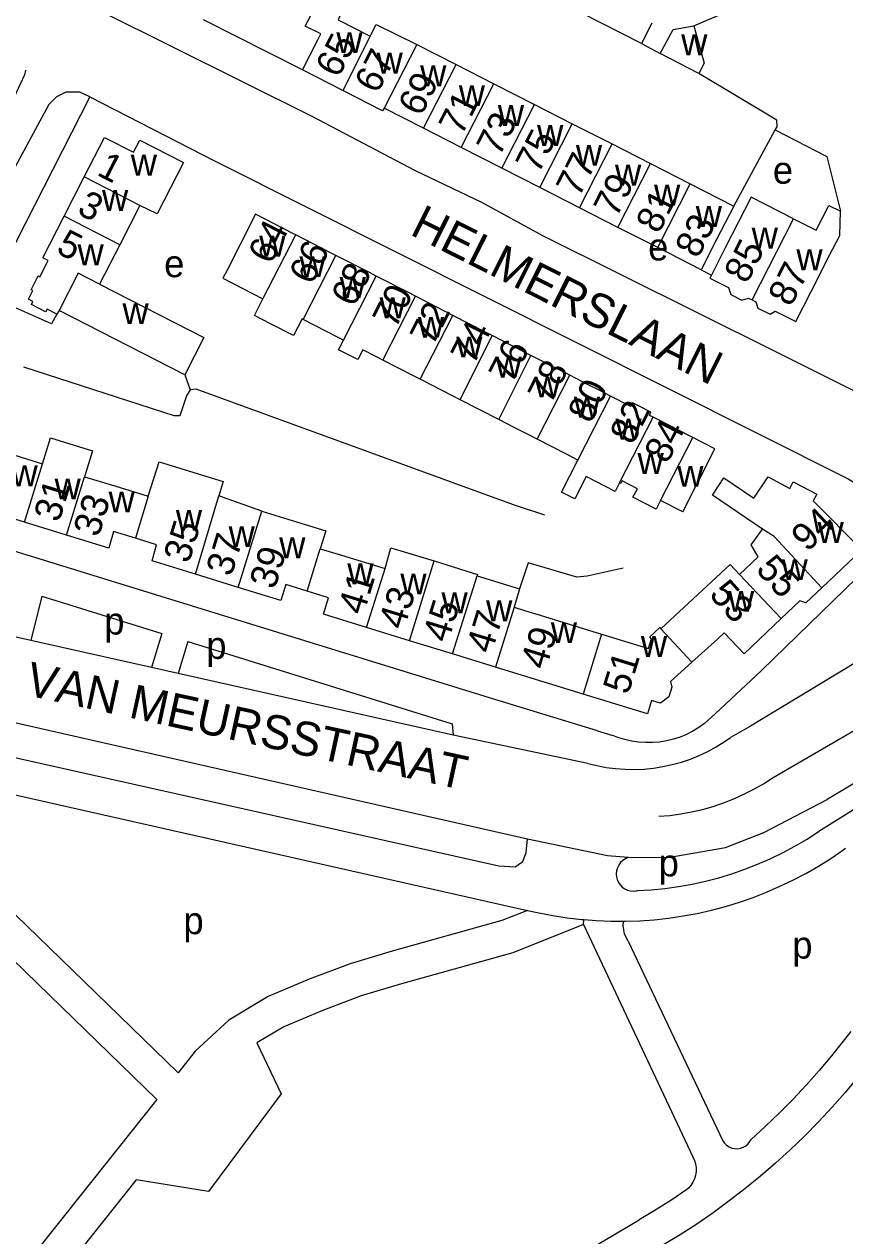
# Model space of a CAD drawing. Extents: x 159700 to 161346, y 381730 to 382922.
# Drawn here: x 161147.7 to 161268.5, y 382139.7 to 382318 of the extents above; entities that cross this region are included whole.
import ezdxf

# ---------------------------------------------------------------- set-up
doc = ezdxf.new("R2010")
doc.units = 0
for name, color, linetype in [('BLT_Basislijn', 7, 'Continuous'), ('BLT_Bebouwing', 7, 'Continuous'), ('BLT_Centroide', 7, 'Continuous'), ('BLT_Huisnummer', 7, 'Continuous'), ('BLT_Huisnummer_ tussenligend', 7, 'Continuous'), ('BLT_Onderverdeling_panden', 7, 'Continuous'), ('BLT_Straatnaam', 7, 'Continuous')]:
    doc.layers.add(name, color=color, linetype=linetype)

msp = doc.modelspace()

# ---------------------------------------------------------------- linework, layer by layer
at = {"layer": 'BLT_Basislijn'}
for p, q in [((161246.29, 382317.8), (161251.01, 382319.8)), ((161188.65, 382311.3), (161174.06, 382318.7)), ((161157.33, 382307.36), (161142.38, 382278.03)), ((161252.16, 382291.27), (161258.27, 382302.47)), ((161247.35, 382281.89), (161248.86, 382281.11)), ((161171.32, 382266.4), (161172.12, 382264.2)), ((161150.27, 382233.83), (161148.65, 382227.32)), ((161150.27, 382233.83), (161167.93, 382228.34)), ((161148.65, 382227.32), (161144.74, 382228.2)), ((161167.93, 382228.34), (161166.4, 382223.34)), ((161257.96, 382207.15), (161294.16, 382228.21)), ((161166.4, 382223.34), (161148.65, 382227.32)), ((161171.75, 382227.15), (161170.32, 382222.46)), ((161273.58, 382226.16), (161254.38, 382214.56)), ((161170.32, 382222.46), (161166.4, 382223.34)), ((161210.83, 382213.38), (161170.32, 382222.46)), ((161232.1, 382213.98), (161215.7, 382219.01)), ((161249.4, 382216.51), (161247.87, 382215.08)), ((161232.1, 382213.98), (161234.33, 382213.33)), ((161254.38, 382214.56), (161251.69, 382213.01)), ((161230.67, 382209.19), (161210.83, 382213.38)), ((161279.52, 382212.11), (161265.92, 382203.87)), ((161122.38, 382209.98), (161221.8, 382187.57)), ((161230.67, 382209.19), (161233.36, 382208.62)), ((161144.83, 382188.45), (161151.35, 382182.11)), ((161230.04, 382185.49), (161230.1, 382186.2)), ((161230.04, 382185.49), (161246.12, 382151.26)), ((161141.19, 382185.02), (161147.87, 382178.52)), ((161151.35, 382182.11), (161170.32, 382163.66)), ((161236.6, 382183.04), (161250.53, 382153.64)), ((161147.87, 382178.52), (161167.19, 382159.73)), ((161269.39, 382169.75), (161266.56, 382166.17)), ((161167.19, 382159.73), (161147.75, 382135.31)), ((161164.16, 382147.9), (161150.96, 382131.31)), ((161226.29, 382134.98), (161238.25, 382142.02))]:
    msp.add_line(p, q, dxfattribs=at)
for points in [[(161298.14, 382325.04), (161299.69, 382317.42), (161300.12, 382311.03), (161299.87, 382302.89), (161298.97, 382296.72), (161298.27, 382293.35), (161296.39, 382286.02), (161292.14, 382276.23), (161285.45, 382261.64), (161283.47, 382257.74), (161282.99, 382257.62), (161282.06, 382257.91), (161259.03, 382269.47)], [(161259.03, 382269.47), (161258.44, 382269.76), (161224.02, 382286.9), (161215.06, 382291.8), (161205.29, 382296.45), (161190.08, 382304.47), (161159.12, 382319.84)], [(161238.56, 382315.19), (161241.34, 382313.71)], [(161147.84, 382311.25), (161147.72, 382310.59), (161145.18, 382305.08)], [(161258.27, 382302.47), (161258.54, 382302.91), (161258.5, 382303.93), (161247.03, 382310.78)], [(161157.33, 382307.36), (161155.87, 382308.04), (161153.79, 382308.04), (161152.42, 382307.37), (161151.3, 382306.22), (161146.63, 382297.57), (161141.2, 382286.87), (161140.09, 382285.05), (161118.46, 382243.46), (161117.44, 382240.72), (161117.66, 382237.93), (161118.49, 382235.91), (161120.31, 382234.05), (161122.64, 382233.1), (161125.14, 382232.59)], [(161157.33, 382307.36), (161175.77, 382297.89), (161269.01, 382251.12), (161279.01, 382245.01)], [(161258.27, 382302.47), (161265.89, 382298.54), (161267.87, 382290.5)], [(161152.48, 382275.35), (161151.71, 382273.93), (161142.38, 382278.03)], [(161215.7, 382219.01), (161214.79, 382219.29), (161134.08, 382244.18), (161130.58, 382245.86), (161129.71, 382246.65), (161128.76, 382248.88), (161128.82, 382251.75), (161138.45, 382270.09)], [(161172.12, 382264.2), (161171.58, 382263.33), (161170.61, 382260.4), (161169.74, 382260.36), (161147.63, 382267.52)], [(161224.33, 382245.76), (161219.71, 382247.26), (161172.98, 382264.31), (161172.12, 382264.2)], [(161279.01, 382245.01), (161256.24, 382222.88), (161249.4, 382216.51)], [(161235.88, 382237.93), (161230.58, 382236.77), (161229.05, 382236.61), (161221.89, 382238.73), (161220.63, 382234.91)], [(161171.75, 382227.15), (161210.67, 382215.05), (161210.83, 382213.38)], [(161131.29, 382218.72), (161140.61, 382216.52), (161221.78, 382198.08)], [(161247.87, 382215.08), (161247.03, 382214.48), (161246.14, 382213.94), (161245.21, 382213.47), (161244.26, 382213.08), (161243.27, 382212.76), (161242.26, 382212.51), (161241.24, 382212.35), (161240.2, 382212.26), (161239.17, 382212.26), (161238.13, 382212.33), (161237.11, 382212.48), (161236.1, 382212.72), (161235.11, 382213.03), (161234.33, 382213.33)], [(161133.09, 382213.02), (161217.57, 382194.12), (161219.96, 382194), (161221.08, 382194.77), (161221.59, 382196.07), (161221.78, 382198.08)], [(161233.36, 382208.62), (161234.75, 382208.44), (161236.15, 382208.34), (161237.55, 382208.32), (161238.95, 382208.38), (161240.35, 382208.52), (161241.73, 382208.73), (161243.1, 382209.03), (161244.45, 382209.4), (161245.78, 382209.85), (161247.08, 382210.38), (161248.35, 382210.97), (161249.58, 382211.64), (161250.77, 382212.38), (161251.69, 382213.01)], [(161279.52, 382212.11), (161280.15, 382208.87), (161264.7, 382199.2)], [(161241.11, 382201.42), (161242.74, 382201.55), (161244.35, 382201.77), (161245.96, 382202.06), (161247.54, 382202.43), (161249.11, 382202.87), (161250.65, 382203.39), (161252.17, 382203.99), (161253.65, 382204.66), (161255.11, 382205.4), (161256.52, 382206.22), (161257.96, 382207.15)], [(161236.62, 382195.42), (161237.4, 382195.37), (161242.77, 382195.39), (161250.94, 382196.81), (161256.59, 382199.01), (161265.92, 382203.87)], [(161221.78, 382198.08), (161233.58, 382195.63), (161236.62, 382195.42)], [(161238, 382190.48), (161240.02, 382190.59), (161242.03, 382190.79), (161244.03, 382191.06), (161246.02, 382191.42), (161248, 382191.85), (161249.95, 382192.36), (161251.89, 382192.94), (161253.8, 382193.61), (161255.68, 382194.35), (161257.53, 382195.16), (161259.35, 382196.04), (161261.13, 382197), (161262.87, 382198.02), (161264.57, 382199.12), (161264.7, 382199.2)], [(161235.9, 382185.97), (161236.18, 382185.97), (161238.32, 382186.04), (161240.45, 382186.19), (161242.57, 382186.43), (161244.69, 382186.74), (161246.79, 382187.13), (161248.88, 382187.61), (161250.94, 382188.15), (161252.99, 382188.78), (161255, 382189.48), (161256.99, 382190.26), (161258.96, 382191.11), (161260.88, 382192.03), (161262.78, 382193.02), (161264.63, 382194.09), (161266.44, 382195.22), (161268.21, 382196.42), (161268.64, 382196.73)], [(161236.62, 382195.42), (161236.2, 382195.15), (161235.82, 382194.91), (161235.49, 382194.6), (161235.22, 382194.24), (161235.02, 382193.84), (161234.89, 382193.41), (161234.85, 382192.97), (161234.88, 382192.52), (161234.99, 382192.09), (161235.17, 382191.68), (161235.42, 382191.31), (161235.74, 382190.99), (161236.11, 382190.73), (161236.51, 382190.54), (161236.95, 382190.43), (161237.4, 382190.4), (161237.84, 382190.44), (161238, 382190.48)], [(161221.8, 382187.57), (161218.03, 382186.06), (161201.85, 382181.57), (161195.69, 382179.7), (161189.64, 382177.43), (161183.61, 382174.87), (161177.82, 382171.4), (161172.83, 382166.82), (161170.32, 382163.66)], [(161221.8, 382187.57), (161223.44, 382187.19), (161225.54, 382186.79), (161227.65, 382186.47), (161229.78, 382186.22), (161230.1, 382186.2)], [(161230.04, 382185.49), (161219.63, 382181.32), (161203.24, 382176.77), (161197.3, 382174.96), (161191.5, 382172.79), (161185.89, 382170.4), (161181.93, 382168.04)], [(161230.1, 382186.2), (161231.91, 382186.06), (161234.04, 382185.97), (161235.9, 382185.97)], [(161236.6, 382183.04), (161236.31, 382183.57), (161236.09, 382184.13), (161235.95, 382184.72), (161235.89, 382185.32), (161235.9, 382185.97)], [(161181.93, 382168.04), (161185.51, 382160.56), (161174.81, 382146.19), (161164.16, 382147.9)], [(161266.56, 382166.17), (161264.73, 382163.98), (161262.83, 382161.83), (161260.88, 382159.74), (161258.87, 382157.71), (161256.8, 382155.73), (161254.72, 382153.84)], [(161270.45, 382163.02), (161268.57, 382160.77), (161266.63, 382158.57), (161264.63, 382156.43), (161262.58, 382154.34), (161260.46, 382152.31), (161258.3, 382150.34), (161256.08, 382148.42), (161253.81, 382146.57), (161251.49, 382144.78), (161249.12, 382143.05), (161246.71, 382141.39), (161244.25, 382139.8), (161241.74, 382138.28), (161240.75, 382137.69)], [(161250.53, 382153.64), (161250.78, 382153.29), (161251.09, 382152.98), (161251.46, 382152.74), (161251.86, 382152.58), (161252.28, 382152.49), (161252.72, 382152.47), (161253.15, 382152.54), (161253.56, 382152.68), (161253.93, 382152.9), (161254.26, 382153.18), (161254.54, 382153.52), (161254.72, 382153.84)], [(161246.12, 382151.26), (161246.36, 382150.76), (161246.52, 382150.23), (161246.6, 382149.68), (161246.6, 382149.13), (161246.53, 382148.58), (161246.37, 382148.05), (161246.14, 382147.54), (161245.85, 382147.08), (161245.48, 382146.66), (161245.26, 382146.46)], [(161245.26, 382146.46), (161242.89, 382144.86), (161240.46, 382143.34), (161238.25, 382142.02)]]:
    msp.add_lwpolyline(points, dxfattribs=at)
at = {"layer": 'BLT_Bebouwing'}
for p, q in [((161238.56, 382315.19), (161226.71, 382321.22)), ((161240.09, 382318.19), (161238.56, 382315.19)), ((161247.03, 382310.78), (161241.34, 382313.71)), ((161211.27, 382312.11), (161216.82, 382309.28)), ((161194.57, 382308.29), (161188.65, 382311.3)), ((161216.82, 382309.28), (161222.81, 382306.22)), ((161206.48, 382302.71), (161200.69, 382305.66)), ((161222.81, 382306.22), (161228.38, 382303.39)), ((161228.38, 382303.39), (161234.23, 382300.41)), ((161212.04, 382299.88), (161206.48, 382302.71)), ((161218.03, 382296.83), (161212.04, 382299.88)), ((161234.23, 382300.41), (161239.89, 382297.52)), ((161223.6, 382293.99), (161218.03, 382296.83)), ((161239.89, 382297.52), (161245.74, 382294.54)), ((161153.53, 382289.76), (161156.51, 382295.57)), ((161245.74, 382294.54), (161252.16, 382291.27)), ((161229.44, 382291.01), (161223.6, 382293.99)), ((161164.71, 382291.37), (161161.74, 382285.56)), ((161235.11, 382288.12), (161229.44, 382291.01)), ((161150.4, 382283.64), (161153.53, 382289.76)), ((161187.65, 382287.02), (161187.34, 382287.18)), ((161192.98, 382284.29), (161187.65, 382287.02)), ((161240.96, 382285.15), (161235.11, 382288.12)), ((161161.74, 382285.56), (161158.77, 382279.75)), ((161247.35, 382281.89), (161240.96, 382285.15)), ((161151.19, 382283.23), (161150.4, 382283.64)), ((161193.58, 382283.99), (161192.98, 382284.29)), ((161198.61, 382281.41), (161193.58, 382283.99)), ((161199.5, 382280.95), (161198.61, 382281.41)), ((161204.25, 382278.52), (161199.5, 382280.95)), ((161205.3, 382277.98), (161204.25, 382278.52)), ((161209.88, 382275.64), (161205.3, 382277.98)), ((161152.81, 382275.88), (161152.48, 382275.35)), ((161171.32, 382266.4), (161152.81, 382275.88)), ((161193.82, 382271.98), (161188.76, 382274.57)), ((161210.81, 382275.16), (161209.88, 382275.64)), ((161215.52, 382272.75), (161210.81, 382275.16)), ((161216.6, 382272.2), (161215.52, 382272.75)), ((161194.68, 382271.54), (161193.82, 382271.98)), ((161221.15, 382269.87), (161216.6, 382272.2)), ((161200.49, 382268.57), (161199.46, 382269.1)), ((161222.3, 382269.28), (161221.15, 382269.87)), ((161228.02, 382266.35), (161222.3, 382269.28)), ((161205.09, 382266.21), (161200.49, 382268.57)), ((161205.96, 382265.77), (161205.09, 382266.21)), ((161210.73, 382263.33), (161205.96, 382265.77)), ((161230.84, 382264.91), (161228.02, 382266.35)), ((161232.42, 382264.1), (161230.84, 382264.91)), ((161234.01, 382263.28), (161232.42, 382264.1)), ((161211.86, 382262.75), (161210.73, 382263.33)), ((161217.56, 382259.83), (161211.86, 382262.75)), ((161219.91, 382258.62), (161217.56, 382259.83)), ((161222, 382257.56), (161219.91, 382258.62)), ((161243.73, 382258.41), (161243.17, 382258.7)), ((161223.21, 382256.94), (161222, 382257.56)), ((161227.63, 382254.67), (161223.21, 382256.94)), ((161143.88, 382255.32), (161150.36, 382253.33)), ((161226.77, 382249.15), (161229.19, 382253.87)), ((161176.97, 382250.72), (161176.31, 382248.58)), ((161182.66, 382246.36), (161176.31, 382248.58)), ((161244.64, 382246.22), (161241.37, 382247.9)), ((161147.71, 382244.73), (161141.23, 382246.73)), ((161153.92, 382242.82), (161147.71, 382244.73)), ((161167.16, 382241.39), (161164.04, 382242.35)), ((161191.26, 382240.82), (161194.4, 382239.85)), ((161179.19, 382235.1), (161172.87, 382237.05)), ((161192.48, 382233.6), (161189.33, 382234.57)), ((161220.63, 382234.91), (161219.8, 382232.21)), ((161204.42, 382227.27), (161198.08, 382229.22)), ((161232.68, 382228.24), (161239.59, 382226.11)), ((161210.75, 382225.32), (161204.42, 382227.27)), ((161249.78, 382227.52), (161246, 382224.12)), ((161217.08, 382223.37), (161210.75, 382225.32)), ((161229.96, 382219.4), (161217.08, 382223.37))]:
    msp.add_line(p, q, dxfattribs=at)
for points in [[(161188.65, 382311.3), (161190.91, 382315.76), (161191.34, 382316.6), (161189.04, 382317.77), (161193.71, 382326.6), (161198.85, 382326.38), (161197.86, 382323.89), (161197.26, 382323.91), (161194.48, 382320.54), (161193.62, 382319.5), (161194.15, 382319.23), (161193.88, 382318.7), (161198.64, 382316.28)], [(161198.64, 382316.28), (161199.5, 382318), (161205.48, 382315.06)], [(161241.34, 382313.71), (161243.23, 382317.26), (161246.29, 382317.8)], [(161246.29, 382317.8), (161247.81, 382312.3), (161247.03, 382310.78)], [(161205.48, 382315.06), (161211.27, 382312.11)], [(161200.69, 382305.66), (161200.45, 382305.29), (161194.57, 382308.29)], [(161156.51, 382295.57), (161159.48, 382301.38), (161163.77, 382299.19), (161164.68, 382300.96), (161171.11, 382297.67), (161167.23, 382290.1), (161164.71, 382291.37)], [(161260.96, 382289.39), (161254.71, 382292.56), (161250.9, 382285.11), (161248.86, 382281.11)], [(161252.16, 382291.27), (161249.62, 382286.34), (161247.35, 382281.89)], [(161260.96, 382289.39), (161264.3, 382287.71), (161266.17, 382291.37), (161267.87, 382290.5)], [(161261.29, 382274.25), (161263.56, 382278.7), (161266.28, 382284.04), (161267.77, 382286.93), (161267.87, 382290.5)], [(161187.34, 382287.18), (161181.74, 382290.05), (161179.46, 382285.6), (161177.54, 382281.84), (161176.92, 382280.63), (161182.83, 382277.61)], [(161152.48, 382275.35), (161151.03, 382276.1), (161150.8, 382275.7), (161148.72, 382276.76), (161148.95, 382277.22), (161148.31, 382277.55), (161148.96, 382278.81), (161148.68, 382278.95), (161149.72, 382280.97), (161149.97, 382280.85), (161151.19, 382283.23)], [(161158.77, 382279.75), (161174.13, 382271.89), (161171.32, 382266.4)], [(161248.86, 382281.11), (161248.63, 382280.66), (161251.39, 382279.25), (161251.72, 382278.23), (161253.36, 382277.39), (161254.35, 382277.72), (161254.89, 382277.44)], [(161187.34, 382272.19), (161183.92, 382273.94), (161181.57, 382275.14), (161182.83, 382277.61)], [(161254.89, 382277.44), (161255.43, 382277.16), (161255.73, 382276.24), (161257.53, 382275.33), (161258.25, 382275.8), (161261.29, 382274.25)], [(161188.76, 382274.57), (161188.6, 382274.66), (161187.34, 382272.19)], [(161199.46, 382269.1), (161197.52, 382270.09), (161196.78, 382268.66), (161193.94, 382270.12), (161194.68, 382271.54)], [(161237, 382261.76), (161236.99, 382261.76), (161234.01, 382263.28)], [(161238.33, 382261.74), (161237.27, 382262.28), (161237, 382261.76)], [(161240.29, 382260.17), (161239.74, 382260.45), (161239.97, 382260.9), (161238.33, 382261.74)], [(161243.17, 382258.7), (161240.29, 382260.17)], [(161246.12, 382257.18), (161243.73, 382258.41)], [(161150.36, 382253.33), (161151.54, 382257.15), (161157.74, 382255.24), (161156.57, 382251.41)], [(161244.64, 382246.22), (161246.57, 382250), (161247.11, 382251.06), (161249.37, 382255.52), (161246.12, 382257.18)], [(161165.94, 382248.53), (161167.52, 382253.63), (161176.97, 382250.72)], [(161229.19, 382253.87), (161227.63, 382254.67)], [(161156.57, 382251.41), (161161.15, 382250), (161165.94, 382248.53)], [(161235.35, 382250.52), (161234.69, 382249.24), (161230.42, 382251.43), (161228.74, 382248.14), (161226.77, 382249.15)], [(161256.38, 382243.71), (161249.01, 382248.72), (161250.69, 382251.24), (161255.11, 382248.25), (161257.25, 382251.42), (161260.41, 382249.69), (161260.93, 382250.67), (161264.39, 382248.85), (161263.83, 382247.87), (161271.02, 382240.67), (161265.11, 382235.07)], [(161241.37, 382247.9), (161240.72, 382246.64), (161237.32, 382248.39), (161237.97, 382249.65), (161235.71, 382250.81), (161235.52, 382250.44), (161235.35, 382250.52)], [(161182.66, 382246.36), (161189.04, 382244.39), (161192.07, 382243.46), (161191.26, 382240.82)], [(161164.04, 382242.35), (161160.83, 382243.34), (161160.12, 382240.91), (161153.92, 382242.82)], [(161252.99, 382237.03), (161255.74, 382239.64), (161254.71, 382241.38), (161256.38, 382243.71)], [(161172.87, 382237.05), (161166.49, 382239.01), (161167.16, 382241.39)], [(161200.81, 382237.88), (161201.65, 382240.94), (161208.04, 382239.01)], [(161194.4, 382239.85), (161200.81, 382237.88)], [(161208.04, 382239.01), (161214.41, 382237.04), (161214.35, 382236.84)], [(161241.44, 382229.04), (161251.61, 382238.48), (161252.99, 382237.03)], [(161189.33, 382234.57), (161186.19, 382235.54), (161185.46, 382233.17), (161179.19, 382235.1)], [(161214.35, 382236.84), (161220.63, 382234.91)], [(161198.08, 382229.22), (161191.74, 382231.18), (161192.48, 382233.6)], [(161265.11, 382235.07), (161262.78, 382232.86), (161261.91, 382233.12), (161259.16, 382230.52)], [(161219.8, 382232.21), (161221.36, 382231.73), (161223.65, 382231.02), (161232.68, 382228.24)], [(161259.16, 382230.52), (161253.69, 382225.33), (161250.77, 382228.41), (161249.78, 382227.52)], [(161239.59, 382226.11), (161240.04, 382227.53), (161239.79, 382227.82), (161241.27, 382229.22), (161241.44, 382229.04)], [(161246, 382224.12), (161242.84, 382221.26), (161243.04, 382220.41), (161242.62, 382219), (161241.37, 382218.08), (161240.06, 382218.48), (161239.45, 382216.48), (161229.96, 382219.4)]]:
    msp.add_lwpolyline(points, dxfattribs=at)
at = {"layer": 'BLT_Onderverdeling_panden'}
for p, q in [((161198.64, 382316.28), (161194.57, 382308.29)), ((161205.48, 382315.06), (161200.69, 382305.66)), ((161206.48, 382302.71), (161211.27, 382312.11)), ((161212.04, 382299.88), (161216.82, 382309.28)), ((161218.03, 382296.83), (161222.81, 382306.22)), ((161223.6, 382293.99), (161228.38, 382303.39)), ((161229.44, 382291.01), (161234.23, 382300.41)), ((161235.11, 382288.12), (161239.89, 382297.52)), ((161164.71, 382291.37), (161156.51, 382295.57)), ((161240.96, 382285.15), (161245.74, 382294.54)), ((161161.74, 382285.56), (161153.53, 382289.76)), ((161254.89, 382277.44), (161260.96, 382289.39)), ((161182.83, 382277.61), (161187.65, 382287.02)), ((161188.76, 382274.57), (161193.58, 382283.99)), ((161155.62, 382281.36), (161152.81, 382275.88)), ((161158.77, 382279.75), (161155.62, 382281.36)), ((161194.68, 382271.54), (161199.5, 382280.95)), ((161200.49, 382268.57), (161205.3, 382277.98)), ((161205.96, 382265.77), (161210.81, 382275.16)), ((161211.86, 382262.75), (161216.6, 382272.2)), ((161217.56, 382259.83), (161222.3, 382269.28)), ((161223.21, 382256.94), (161228.02, 382266.35)), ((161229.19, 382253.87), (161234.01, 382263.28)), ((161235.35, 382250.52), (161240.29, 382260.17)), ((161241.37, 382247.9), (161246.12, 382257.18)), ((161147.71, 382244.73), (161150.36, 382253.33)), ((161153.92, 382242.82), (161156.57, 382251.41)), ((161165.94, 382248.53), (161164.04, 382242.35)), ((161172.87, 382237.05), (161176.31, 382248.58)), ((161179.19, 382235.1), (161182.66, 382246.36)), ((161189.33, 382234.57), (161191.26, 382240.82)), ((161204.42, 382227.27), (161208.04, 382239.01)), ((161198.08, 382229.22), (161200.81, 382237.88)), ((161259.16, 382230.52), (161252.99, 382237.03)), ((161210.75, 382225.32), (161214.35, 382236.84)), ((161219.8, 382232.21), (161217.08, 382223.37)), ((161232.68, 382228.24), (161229.96, 382219.4)), ((161246, 382224.12), (161241.44, 382229.04))]:
    msp.add_line(p, q, dxfattribs=at)
msp.add_lwpolyline([(161265.11, 382235.07), (161258.09, 382242.63), (161256.38, 382243.71)], dxfattribs=at)

# ---------------------------------------------------------------- texts
at = {"layer": 'BLT_Centroide'}
for s, p in [('w', (161193.64, 382313.78)), ('w', (161244.42, 382313.47)), ('w', (161199.56, 382310.78)), ('w', (161205.98, 382308.89)), ('w', (161211.66, 382305.98)), ('w', (161217.42, 382303.05)), ('w', (161223.2, 382300.11)), ('w', (161228.91, 382297.2)), ('w', (161163.36, 382295.75)), ('e', (161257.92, 382294.55)), ('w', (161234.67, 382294.27)), ('w', (161240.42, 382291.33)), ('w', (161159.12, 382290.56)), ('w', (161246.56, 382288.2)), ('w', (161182.28, 382283.83)), ('w', (161254.8, 382285)), ('w', (161155.52, 382282.56)), ('e', (161239.56, 382283.26)), ('e', (161168.28, 382280.79)), ('w', (161188.2, 382280.8)), ('w', (161261.38, 382281.81)), ('w', (161194.12, 382277.75)), ('w', (161162.14, 382273.88)), ('w', (161200, 382274.75)), ('w', (161205.64, 382271.88)), ('w', (161211.28, 382268.98)), ('w', (161217.08, 382266.02)), ('w', (161222.8, 382263.09)), ('w', (161228.61, 382260.11)), ('w', (161234.73, 382256.88)), ('w', (161237.99, 382251.82)), ('w', (161145.8, 382250.02)), ('w', (161243.84, 382249.94)), ('w', (161152.14, 382248.08)), ('w', (161160.09, 382246.16)), ('w', (161170, 382243.45)), ('w', (161177.77, 382241.06)), ('w', (161264.5, 382241.66)), ('w', (161185.22, 382239.41)), ('w', (161259.2, 382236.19)), ('w', (161195.25, 382235.58)), ('w', (161203.06, 382234.09)), ('w', (161209.12, 382231.3)), ('w', (161251.31, 382231.53)), ('w', (161215.69, 382230.12)), ('p', (161159.46, 382228.18)), ('w', (161225.22, 382226.91)), ('p', (161174.48, 382224.59)), ('w', (161238.48, 382224.88)), ('p', (161241.1, 382192.57)), ('p', (161171.12, 382184.06)), ('p', (161260.78, 382180.47))]:
    msp.add_text(s, height=4, dxfattribs=at).set_placement(p)
at = {"layer": 'BLT_Huisnummer'}
for s, rotation, p in [('65', 63.0035, (161193.94, 382309.99)), ('69', 63.0049, (161206.11, 382304.31)), ('73', 63.0073, (161217.64, 382298.41)), ('1', 332.8903, (161158.21, 382295.9)), ('77', 63.0047, (161229.36, 382292.4)), ('81', 63.0046, (161241.1, 382287.04)), ('64', 63.0659, (161184.01, 382282.53)), ('5', 332.8875, (161152.2, 382284.46)), ('85', 63.007, (161254.1, 382279.68)), ('68', 63.0645, (161196.23, 382276.24)), ('87', 62.9385, (161260.58, 382276.29)), ('72', 63.0631, (161207.83, 382270.5)), ('76', 63.0631, (161219.45, 382264.94)), ('80', 63.0627, (161231.1, 382259.11)), ('84', 63.0864, (161242.36, 382253.17)), ('31', 72.8837, (161152.81, 382244.56)), ('94', 43.458, (161262.98, 382240.22)), ('35', 72.881, (161171.91, 382238.51)), ('39', 72.8815, (161184.57, 382234.69)), ('55', 312.0185, (161255.26, 382237.68)), ('41', 72.8808, (161197.62, 382230.91)), ('43', 72.8808, (161203.58, 382228.74)), ('47', 72.8836, (161216.49, 382225.22)), ('51', 72.8631, (161236.62, 382219.2))]:
    msp.add_text(s, height=4, rotation=rotation, dxfattribs=at).set_placement(p)
at = {"layer": 'BLT_Huisnummer_ tussenligend'}
for s, rotation, p in [('67', 63.0035, (161199.69, 382307.67)), ('71', 63.0049, (161212.08, 382301.49)), ('75', 63.0073, (161223.4, 382295.87)), ('79', 63.0047, (161234.89, 382289.41)), ('3', 332.8903, (161155.28, 382290.21)), ('83', 63.0046, (161246.88, 382283.41)), ('66', 63.0659, (161190.04, 382279.51)), ('70', 63.0645, (161202.34, 382273.05)), ('74', 63.0631, (161213.84, 382267.71)), ('78', 63.0631, (161225.19, 382261.92)), ('82', 63.0627, (161237.27, 382255.96)), ('33', 72.8837, (161158.63, 382242.38)), ('37', 72.881, (161178.17, 382236.58)), ('53', 312.0235, (161248.39, 382234)), ('45', 72.8836, (161210.08, 382226.84)), ('49', 72.8804, (161224.48, 382222.86))]:
    msp.add_text(s, height=4, rotation=rotation, dxfattribs=at).set_placement(p)
at = {"layer": 'BLT_Straatnaam'}
for s, height, rotation, p in [('HELMERSLAAN', 5, 333.361, (161204.3, 382287.14)), ('VAN MEURSSTRAAT', 4.9999, 347.7351, (161147.66, 382219.32))]:
    msp.add_text(s, height=height, rotation=rotation, dxfattribs=at).set_placement(p)

doc.saveas('drawing.dxf')
